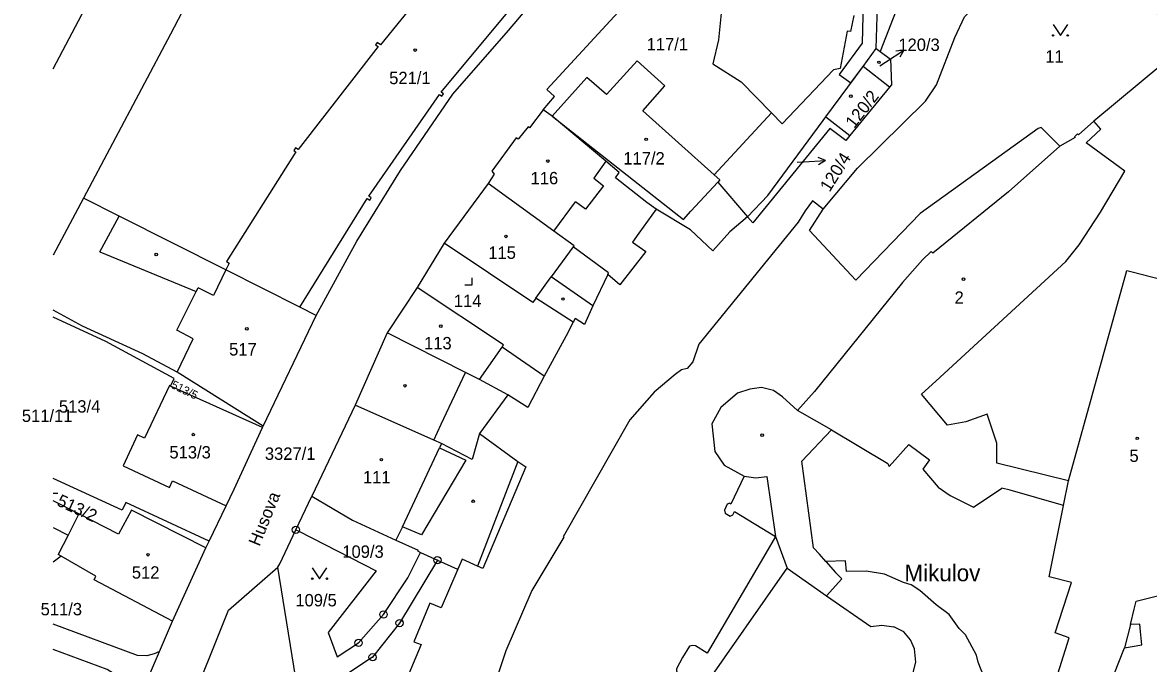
# Model space of a CAD drawing. Extents: x -600849 to -599899, y -1204328 to -1203436.
# Drawn here: x -600847.4 to -600692.7, y -1203896.5 to -1203808.4 of the extents above; entities that cross this region are included whole.
import ezdxf

# ---------------------------------------------------------------- set-up
doc = ezdxf.new("R2010")
doc.units = 0
for name, color, linetype in [('Vrstva 1', 7, 'Continuous'), ('Vrstva 13', 7, 'Continuous'), ('Vrstva 2', 7, 'Continuous'), ('Vrstva 3', 7, 'Continuous'), ('Vrstva 4', 7, 'Continuous'), ('Vrstva 5', 7, 'Continuous'), ('Vrstva 7', 7, 'Continuous'), ('Vrstva 8', 7, 'Continuous')]:
    doc.layers.add(name, color=color, linetype=linetype)

msp = doc.modelspace()

# ---------------------------------------------------------------- linework, layer by layer
at = {"layer": 'Vrstva 1'}
for p, q in [((-600727.05, -1203805.97), (-600729.55, -1203812.41)), ((-600737.03, -1203821.39), (-600731.91, -1203814.47)), ((-600728.27, -1203817.33), (-600731.91, -1203814.47)), ((-600728.27, -1203817.33), (-600733.72, -1203823.97)), ((-600774.6, -1203821.28), (-600775.84, -1203820.43)), ((-600745, -1203832.19), (-600737.4, -1203821.9)), ((-600737.4, -1203821.9), (-600737.03, -1203821.39)), ((-600737.03, -1203821.39), (-600733.72, -1203823.97)), ((-600783.42, -1203830.57), (-600789.47, -1203838.73)), ((-600839.01, -1203832.56), (-600843.16, -1203840.38)), ((-600747.78, -1203835.11), (-600745, -1203832.19)), ((-600760.31, -1203834.09), (-600762.69, -1203837.37)), ((-600807.05, -1203848.68), (-600801.44, -1203838.45)), ((-600789.47, -1203838.73), (-600793.16, -1203844.82)), ((-600771.73, -1203839.24), (-600771.6, -1203839.09)), ((-600809.28, -1203847.56), (-600819.46, -1203842.42)), ((-600793.16, -1203844.82), (-600797.28, -1203851.06)), ((-600839.14, -1203850.16), (-600843.16, -1203847.96)), ((-600814.3, -1203863.89), (-600807.05, -1203848.68)), ((-600807.05, -1203848.68), (-600809.28, -1203847.56)), ((-600830.86, -1203853.93), (-600839.14, -1203850.16)), ((-600780.72, -1203859.56), (-600784.58, -1203857.49)), ((-600814.39, -1203864.09), (-600827.03, -1203858.37)), ((-600780.72, -1203859.56), (-600784.61, -1203864.9)), ((-600738.59, -1203859.1), (-600740.89, -1203861.71)), ((-600814.39, -1203864.09), (-600814.3, -1203863.89)), ((-600784.61, -1203864.9), (-600779.31, -1203868.72)), ((-600809.81, -1203878.13), (-600807.64, -1203873.51)), ((-600821.74, -1203879.69), (-600819.41, -1203874.84)), ((-600822.18, -1203880.62), (-600821.74, -1203879.69)), ((-600826.76, -1203890.67), (-600822.18, -1203880.62)), ((-600793.09, -1203881.03), (-600792.7, -1203881.25)), ((-600792.7, -1203881.25), (-600790.38, -1203882.29)), ((-600737.9, -1203881.45), (-600738.72, -1203880.62)), ((-600734.19, -1203883.86), (-600734.3, -1203882.37)), ((-600809.25, -1203902.22), (-600812.31, -1203883.27)), ((-600826.76, -1203890.67), (-600837.53, -1203884.98)), ((-600828.56, -1203894.86), (-600826.76, -1203890.67)), ((-600831.48, -1203901.67), (-600828.56, -1203894.86))]:
    msp.add_line(p, q, dxfattribs=at)
for points in [[(-600802.64, -1203748.13), (-600803.14, -1203749.18), (-600814.03, -1203785.11), (-600827.06, -1203810.04), (-600839.01, -1203832.56)], [(-600737.38, -1203834.09), (-600732.67, -1203828.46), (-600723.35, -1203819.26), (-600721.81, -1203816.98), (-600719.31, -1203810.49), (-600717.95, -1203807.66), (-600716.14, -1203805.77), (-600712.27, -1203803.58), (-600705.39, -1203801.39), (-600697.84, -1203798.69), (-600687.98, -1203794.26), (-600682.65, -1203790.56), (-600667.7, -1203784.66)], [(-600673.9, -1203792.73), (-600675.35, -1203794.62), (-600677.86, -1203792.55), (-600681.23, -1203794.3), (-600693.25, -1203805.47), (-600687.48, -1203811.4), (-600700.22, -1203821.97)], [(-600843.16, -1203814.79), (-600834.4, -1203798.18), (-600843.16, -1203793.49)], [(-600787.03, -1203797.7), (-600798.21, -1203811.49), (-600798.63, -1203811.16), (-600798.87, -1203811.48), (-600798.52, -1203811.75), (-600809.52, -1203825.88), (-600809.86, -1203825.65), (-600810.09, -1203826.01), (-600809.82, -1203826.18), (-600819.35, -1203841.27), (-600819, -1203841.47), (-600819.46, -1203842.42)], [(-600801.44, -1203838.45), (-600795.45, -1203828.75), (-600788.25, -1203818.26), (-600780.62, -1203809.55), (-600775.47, -1203803.45), (-600771.22, -1203798.52)], [(-600775.84, -1203820.43), (-600774.28, -1203818.6), (-600775.35, -1203817.62), (-600759.61, -1203800.52), (-600755.85, -1203801.01)], [(-600755.85, -1203801.01), (-600755.86, -1203801.21), (-600756.54, -1203801.19), (-600756.54, -1203802.08), (-600754.02, -1203802.09), (-600753.97, -1203801.76), (-600750.89, -1203802.05), (-600751.77, -1203810.82), (-600752.53, -1203814.09), (-600748.64, -1203816.56), (-600744.48, -1203820.82), (-600752.36, -1203829.34)], [(-600809.28, -1203847.56), (-600800.02, -1203832.63), (-600799.67, -1203832.86), (-600799.46, -1203832.53), (-600799.81, -1203832.3), (-600790.11, -1203818.32), (-600789.79, -1203818.55), (-600789.56, -1203818.22), (-600789.87, -1203817.98), (-600778.94, -1203804.83)], [(-600731.91, -1203814.47), (-600730.1, -1203812.01), (-600729.55, -1203812.41)], [(-600729.55, -1203812.41), (-600728.12, -1203813.46), (-600728, -1203817), (-600728.27, -1203817.33)], [(-600752.36, -1203829.34), (-600762.17, -1203820.56), (-600759.15, -1203817.12), (-600762.96, -1203813.69), (-600767.14, -1203818.32), (-600769.85, -1203815.97), (-600774.6, -1203821.28)], [(-600775.84, -1203820.43), (-600777.71, -1203822.91), (-600777.92, -1203822.75), (-600779.3, -1203824.45), (-600779.56, -1203824.27), (-600782.92, -1203828.86)], [(-600765.91, -1203829.78), (-600765.41, -1203829.03), (-600767.23, -1203827.5), (-600774.6, -1203821.28)], [(-600700.22, -1203821.97), (-600702.31, -1203823.86), (-600702.44, -1203823.71), (-600702.87, -1203824.15), (-600702.76, -1203824.25), (-600704.9, -1203825.4)], [(-600701.28, -1203824.96), (-600699.26, -1203823.08), (-600700.22, -1203821.97)], [(-600733.72, -1203823.97), (-600734.29, -1203824.66), (-600736.45, -1203823.01), (-600747.06, -1203835.95), (-600747.78, -1203835.11)], [(-600704.9, -1203825.4), (-600706.94, -1203823.34), (-600707.42, -1203822.85), (-600707.87, -1203823.01), (-600724.08, -1203834.67), (-600732.9, -1203843.81), (-600739.28, -1203837), (-600737.38, -1203834.09)], [(-600704.9, -1203825.4), (-600711.93, -1203831.7), (-600722.33, -1203840.12), (-600722.54, -1203839.9), (-600723.75, -1203841.03), (-600726.51, -1203844.14), (-600738.59, -1203859.1)], [(-600699.3, -1203834.48), (-600695.97, -1203828.84), (-600701.28, -1203824.96)], [(-600782.92, -1203828.86), (-600782.59, -1203829.26), (-600783.42, -1203830.57)], [(-600760.31, -1203834.09), (-600761.62, -1203833.14), (-600765.91, -1203829.78)], [(-600752.36, -1203829.34), (-600751.58, -1203830.04), (-600751.87, -1203830.36), (-600747.78, -1203835.11)], [(-600771.6, -1203839.09), (-600774.37, -1203837.09), (-600783.42, -1203830.57)], [(-600819.46, -1203842.42), (-600834.1, -1203835.04), (-600839.01, -1203832.56)], [(-600737.38, -1203834.09), (-600738.87, -1203832.92), (-600739.85, -1203834.3), (-600740.81, -1203835.88), (-600754.48, -1203852.63), (-600755.3, -1203855.06)], [(-600747.78, -1203835.11), (-600750.21, -1203837.21), (-600752.56, -1203839.78), (-600755.62, -1203836.92), (-600760.31, -1203834.09)], [(-600723.87, -1203859.5), (-600721.91, -1203857.69), (-600704.07, -1203841.28), (-600702.22, -1203838.96), (-600699.3, -1203834.48)], [(-600762.69, -1203837.37), (-600763.6, -1203838.62), (-600761.75, -1203839.9), (-600765.31, -1203844.46), (-600766.97, -1203843.04)], [(-600771.72, -1203849.61), (-600776.85, -1203846.31), (-600777.25, -1203846.89), (-600789.47, -1203838.73)], [(-600766.97, -1203843.04), (-600766.86, -1203842.8), (-600771.73, -1203839.24)], [(-600703.69, -1203871.38), (-600695.68, -1203842.51), (-600695.14, -1203842.65), (-600690.69, -1203843.79)], [(-600766.97, -1203843.04), (-600769.03, -1203847.34), (-600770.16, -1203849.91), (-600771.46, -1203849.1), (-600771.72, -1203849.61)], [(-600775.69, -1203857.03), (-600781.5, -1203853.03), (-600781.29, -1203852.73), (-600793.16, -1203844.82)], [(-600827.03, -1203858.37), (-600826.54, -1203857.35), (-600835.91, -1203852.25), (-600843.16, -1203848.91)], [(-600771.72, -1203849.61), (-600772.69, -1203851.49), (-600775.69, -1203857.03)], [(-600797.28, -1203851.06), (-600801.66, -1203861), (-600807.64, -1203873.51)], [(-600784.58, -1203857.49), (-600786.51, -1203856.53), (-600797.28, -1203851.06)], [(-600695.18, -1203891.11), (-600694.68, -1203889.04), (-600694.39, -1203887.92), (-600690.34, -1203886.92), (-600689.28, -1203885.9), (-600688.55, -1203884.24), (-600688.96, -1203881.25), (-600688.02, -1203881.41), (-600686.37, -1203873.21), (-600684.56, -1203873.7), (-600684.15, -1203869.75), (-600685.6, -1203869.38), (-600682.53, -1203852.21)], [(-600814.3, -1203863.89), (-600826.12, -1203856.48), (-600830.86, -1203853.93)], [(-600755.3, -1203855.06), (-600756.07, -1203855.96), (-600756.84, -1203856.15), (-600757.72, -1203856.79), (-600760.58, -1203859.21), (-600763.94, -1203863)], [(-600775.69, -1203857.03), (-600777.96, -1203861.34), (-600780.72, -1203859.56)], [(-600827.03, -1203858.37), (-600827.18, -1203858.3), (-600830.62, -1203865.52), (-600831.56, -1203865.08), (-600833.54, -1203869.32), (-600827.17, -1203872.3), (-600826.75, -1203871.41), (-600819.41, -1203874.84)], [(-600745.84, -1203858.58), (-600747.47, -1203858.82), (-600749.15, -1203859.36), (-600751.46, -1203861.32), (-600752.69, -1203863.58), (-600752.27, -1203867.37), (-600750.97, -1203869.26)], [(-600740.89, -1203861.71), (-600742.96, -1203859.85), (-600744.19, -1203859), (-600745.84, -1203858.58)], [(-600714.86, -1203862.25), (-600717.79, -1203863.3), (-600720.31, -1203863.73), (-600723.87, -1203859.5)], [(-600738.72, -1203880.62), (-600740.32, -1203868.69), (-600736.22, -1203864.38), (-600740.89, -1203861.71)], [(-600703.69, -1203871.38), (-600713.55, -1203868.98), (-600713.51, -1203866.24), (-600714.86, -1203862.25)], [(-600819.41, -1203874.84), (-600818.29, -1203872.52), (-600814.39, -1203864.09)], [(-600763.94, -1203863), (-600773.1, -1203879.07), (-600772.99, -1203879.14), (-600777.42, -1203886.44), (-600780.99, -1203894.73), (-600783.52, -1203902.47), (-600784.83, -1203907.67), (-600785.24, -1203911.84), (-600785.51, -1203922.73), (-600784.83, -1203931.21)], [(-600779.31, -1203868.72), (-600778.24, -1203869.49), (-600784.16, -1203883.42), (-600784.87, -1203883.1), (-600786.99, -1203882.17), (-600787.58, -1203883.54)], [(-600750.97, -1203869.26), (-600748.24, -1203870.77), (-600750.05, -1203874.59)], [(-600821.74, -1203879.69), (-600833.16, -1203874.39), (-600833.68, -1203875.44), (-600843.16, -1203871.07)], [(-600715.32, -1203921), (-600710.97, -1203917.16), (-600710.86, -1203915.92), (-600707.36, -1203904.89), (-600708.72, -1203904.43), (-600707.81, -1203901.53), (-600706.45, -1203902), (-600703.58, -1203892.95), (-600705.52, -1203892.28), (-600703.27, -1203885.38), (-600706.32, -1203884.59), (-600704.37, -1203874.77), (-600703.69, -1203871.38)], [(-600807.64, -1203873.51), (-600802.06, -1203876.78), (-600796.07, -1203879.54)], [(-600822.18, -1203880.62), (-600832.41, -1203875.44), (-600834.19, -1203878.72), (-600839.64, -1203875.94), (-600843.16, -1203874.14)], [(-600750.05, -1203874.59), (-600750.21, -1203874.47), (-600750.59, -1203874.61), (-600750.93, -1203875.42), (-600750.87, -1203875.84)], [(-600750.87, -1203875.84), (-600750.17, -1203876.23), (-600749.78, -1203876.05), (-600749.56, -1203875.61), (-600743.94, -1203879.03), (-600745.28, -1203881.33), (-600753.32, -1203895.09), (-600754.91, -1203894.07), (-600755.28, -1203894), (-600755.73, -1203894.09), (-600756.69, -1203895.65), (-600757.54, -1203897.2), (-600757.54, -1203897.49), (-600757.43, -1203897.77), (-600755.55, -1203898.91), (-600764.93, -1203914.97)], [(-600812.31, -1203883.27), (-600812, -1203882.78), (-600809.81, -1203878.13)], [(-600809.81, -1203878.13), (-600809.42, -1203878.33), (-600798.77, -1203883.75), (-600805.4, -1203892.23), (-600804.16, -1203895.57), (-600801.2, -1203893.64), (-600797.79, -1203889.76), (-600794.42, -1203884.74), (-600792.7, -1203881.25)], [(-600796.07, -1203879.54), (-600793.03, -1203880.91), (-600793.09, -1203881.03)], [(-600734.3, -1203882.37), (-600737.01, -1203882.46), (-600737.9, -1203881.45)], [(-600837.53, -1203884.98), (-600837.28, -1203884.47), (-600842.06, -1203881.74), (-600843.16, -1203882.57)], [(-600790.38, -1203882.29), (-600795.57, -1203890.93), (-600799.28, -1203895.63), (-600809.25, -1203902.22)], [(-600790.38, -1203882.29), (-600787.62, -1203883.52), (-600787.58, -1203883.54)], [(-600824.88, -1203903.67), (-600819.09, -1203889.18), (-600812.31, -1203883.27)], [(-600787.58, -1203883.54), (-600789.86, -1203888.84), (-600791.4, -1203888.21), (-600793.62, -1203893.51), (-600792.62, -1203893.88), (-600795.05, -1203899.63), (-600790.58, -1203900.68), (-600790.6, -1203903.65), (-600793.26, -1203903.01), (-600793.31, -1203903.54), (-600790.7, -1203904.24), (-600790.71, -1203904.87), (-600793.43, -1203904.71), (-600793.41, -1203905.37), (-600790.81, -1203905.49), (-600791.3, -1203910.49), (-600798.28, -1203911.49), (-600798.81, -1203910.12), (-600799.34, -1203910.23), (-600798.91, -1203911.53), (-600803.11, -1203912.34)], [(-600721.63, -1203913.91), (-600720.73, -1203913.53), (-600719.73, -1203912.59), (-600719.28, -1203911.86), (-600718.71, -1203911.03), (-600717.34, -1203907.4), (-600716.32, -1203905.14), (-600715.97, -1203902.37), (-600715.44, -1203900.22), (-600715.17, -1203898.49), (-600715.7, -1203897.34), (-600716.11, -1203896.32), (-600716.32, -1203895.35), (-600717.85, -1203892.57), (-600718.69, -1203891.67), (-600720.06, -1203889.76), (-600721.86, -1203888.42), (-600724.12, -1203886.44), (-600725.3, -1203885.67), (-600726.35, -1203885.35), (-600728.96, -1203884.22), (-600731.48, -1203883.79), (-600734.19, -1203883.86)], [(-600828.56, -1203894.86), (-600829.27, -1203895.16), (-600830.27, -1203895.42), (-600831.58, -1203895.4), (-600843.16, -1203891.09)], [(-600702.77, -1203919.65), (-600695.52, -1203898.79), (-600697.44, -1203898.03), (-600695.99, -1203894.35), (-600693.6, -1203893.94), (-600693.78, -1203892.09)], [(-600693.78, -1203892.09), (-600693.88, -1203891.09), (-600695.18, -1203891.11)], [(-600831.48, -1203901.67), (-600832.07, -1203900.59), (-600833.17, -1203899.21), (-600834.22, -1203898.26), (-600835.73, -1203897.33), (-600843.16, -1203894.56)]]:
    msp.add_lwpolyline(points, dxfattribs=at)
at = {"layer": 'Vrstva 13'}
msp.add_lwpolyline([(-600729.88, -1203804.64), (-600731.83, -1203803.72), (-600732.02, -1203811.26), (-600735.19, -1203815.56), (-600733.58, -1203816.72), (-600731.91, -1203814.47), (-600730.1, -1203812.01)], close=True, dxfattribs=at)
at = {"layer": 'Vrstva 3'}
for p, q in [((-600785.6, -1203844.49), (-600785.6, -1203843.49)), ((-600786.6, -1203844.49), (-600785.6, -1203844.49)), ((-600843.16, -1203873.08), (-600842.5, -1203873.08))]:
    msp.add_line(p, q, dxfattribs=at)
for points in [[(-600705.8, -1203808.71), (-600704.8, -1203810.21), (-600703.8, -1203808.71)], [(-600807.56, -1203883.34), (-600806.56, -1203884.84), (-600805.56, -1203883.34)]]:
    msp.add_lwpolyline(points, dxfattribs=at)
for centre in [(-600705.8, -1203810.21), (-600703.8, -1203810.21), (-600807.56, -1203884.84), (-600805.56, -1203884.84)]:
    msp.add_circle(centre, 0.1, dxfattribs=at)
at = {"layer": 'Vrstva 4'}
for p, q in [((-600733.18, -1203807.46), (-600733.61, -1203809.69)), ((-600734.08, -1203809.6), (-600735.07, -1203814.73)), ((-600733.61, -1203809.69), (-600734.08, -1203809.6)), ((-600735.96, -1203814.95), (-600743.03, -1203822.35)), ((-600735.07, -1203814.73), (-600735.96, -1203814.95)), ((-600743.03, -1203822.35), (-600744.48, -1203820.82)), ((-600774.6, -1203821.28), (-600756.59, -1203835.51)), ((-600767.23, -1203827.5), (-600768.87, -1203829.81)), ((-600768.87, -1203829.81), (-600767.57, -1203830.87)), ((-600751.87, -1203830.36), (-600755.55, -1203834.37)), ((-600767.57, -1203830.87), (-600770.05, -1203834.07)), ((-600774.37, -1203837.09), (-600771.39, -1203833.08)), ((-600770.05, -1203834.07), (-600771.39, -1203833.08)), ((-600836.77, -1203839.93), (-600834.1, -1203835.04)), ((-600756.59, -1203835.51), (-600755.55, -1203834.37)), ((-600771.73, -1203839.24), (-600774.77, -1203843.37)), ((-600836.77, -1203839.93), (-600823.5, -1203845.39)), ((-600819.46, -1203842.42), (-600821.12, -1203845.93)), ((-600776.85, -1203846.31), (-600774.77, -1203843.37)), ((-600769.03, -1203847.34), (-600774.77, -1203843.37)), ((-600826.19, -1203850.68), (-600823.5, -1203845.39)), ((-600823.5, -1203845.39), (-600823.24, -1203844.88)), ((-600821.12, -1203845.93), (-600823.24, -1203844.88)), ((-600823.93, -1203851.87), (-600826.19, -1203850.68)), ((-600826.12, -1203856.48), (-600823.93, -1203851.87)), ((-600784.58, -1203857.49), (-600781.5, -1203853.03)), ((-600789.86, -1203863.61), (-600786.51, -1203856.53)), ((-600790.89, -1203865.79), (-600801.66, -1203861)), ((-600790.89, -1203865.79), (-600789.86, -1203863.61)), ((-600736.22, -1203864.38), (-600728.5, -1203869)), ((-600789.8, -1203866.27), (-600790.89, -1203865.79)), ((-600784.61, -1203864.9), (-600785.6, -1203868.47)), ((-600795.16, -1203877.71), (-600790.07, -1203866.84)), ((-600789.8, -1203866.27), (-600790.07, -1203866.84)), ((-600790.07, -1203866.84), (-600786.46, -1203868.56)), ((-600785.6, -1203868.47), (-600789.8, -1203866.27)), ((-600728.3, -1203869.41), (-600725.63, -1203866.42)), ((-600725.63, -1203866.42), (-600722.78, -1203868.53)), ((-600786.46, -1203868.56), (-600792.58, -1203878.8)), ((-600779.31, -1203868.72), (-600784.87, -1203883.1)), ((-600728.5, -1203869), (-600728.3, -1203869.41)), ((-600722.78, -1203868.53), (-600723.71, -1203869.79)), ((-600723.71, -1203869.79), (-600721.59, -1203872.26)), ((-600748.24, -1203870.77), (-600746.62, -1203870.99)), ((-600746.62, -1203870.99), (-600745.12, -1203870.8)), ((-600745.12, -1203870.8), (-600743.94, -1203879.03)), ((-600721.59, -1203872.26), (-600719.96, -1203873.41)), ((-600719.96, -1203873.41), (-600716.74, -1203875.01)), ((-600716.74, -1203875.01), (-600712.83, -1203872.41)), ((-600711.69, -1203872.67), (-600712.83, -1203872.41)), ((-600704.37, -1203874.77), (-600711.69, -1203872.67)), ((-600839.64, -1203875.94), (-600841.11, -1203878.86)), ((-600843.16, -1203877.79), (-600841.11, -1203878.86)), ((-600795.16, -1203877.71), (-600796.07, -1203879.54)), ((-600792.58, -1203878.8), (-600795.16, -1203877.71)), ((-600841.11, -1203878.86), (-600842.45, -1203881.52)), ((-600743.94, -1203879.03), (-600742.35, -1203883.41)), ((-600842.06, -1203881.74), (-600842.45, -1203881.52)), ((-600737.01, -1203882.46), (-600735.68, -1203883.97)), ((-600764.48, -1203915.04), (-600742.35, -1203883.41)), ((-600742.35, -1203883.41), (-600736.91, -1203887.2)), ((-600735.68, -1203883.97), (-600734.82, -1203884.86)), ((-600734.82, -1203884.86), (-600736.91, -1203887.2)), ((-600736.91, -1203887.2), (-600730.85, -1203891.41)), ((-600730.85, -1203891.41), (-600729.33, -1203891.2)), ((-600729.33, -1203891.2), (-600727.66, -1203891.47)), ((-600726.29, -1203892.16), (-600727.66, -1203891.47)), ((-600725.41, -1203893.22), (-600726.29, -1203892.16)), ((-600695.18, -1203891.11), (-600695.99, -1203894.35)), ((-600724.82, -1203894.49), (-600725.41, -1203893.22)), ((-600724.67, -1203896.29), (-600724.82, -1203894.49)), ((-600725.08, -1203897.91), (-600724.67, -1203896.29))]:
    msp.add_line(p, q, dxfattribs=at)
at = {"layer": 'Vrstva 5'}
for centre in [(-600793.43, -1203812.22), (-600729.73, -1203813.91), (-600733.59, -1203818.56), (-600761.7, -1203824.48), (-600775.21, -1203827.47), (-600780.96, -1203837.82), (-600829, -1203840.31), (-600718.11, -1203843.69), (-600773.13, -1203846.42), (-600816.56, -1203850.52), (-600789.92, -1203850.14), (-600794.83, -1203858.33), (-600823.91, -1203865.04), (-600745.77, -1203865.12), (-600694.24, -1203865.55), (-600798.08, -1203868.49), (-600785.46, -1203874.2), (-600830.13, -1203881.55)]:
    msp.add_circle(centre, 0.175, dxfattribs=at)
at = {"layer": 'Vrstva 7'}
for p, q in [((-600728.81, -1203813.87), (-600726.29, -1203812.24)), ((-600726.29, -1203812.24), (-600727.41, -1203812.36)), ((-600726.29, -1203812.24), (-600726.86, -1203813.2)), ((-600729.6, -1203814.38), (-600728.81, -1203813.87)), ((-600737.06, -1203827.41), (-600738.09, -1203826.97)), ((-600740.98, -1203827.62), (-600740.06, -1203827.57)), ((-600740.06, -1203827.57), (-600737.06, -1203827.41)), ((-600737.06, -1203827.41), (-600738.04, -1203827.97))]:
    msp.add_line(p, q, dxfattribs=at)
at = {"layer": 'Vrstva 8'}
for centre, radius in [((-600809.81, -1203878.13), 0.5), ((-600809.81, -1203878.13), 0.0303), ((-600790.38, -1203882.29), 0.5), ((-600790.38, -1203882.29), 0.0303), ((-600797.79, -1203889.76), 0.5), ((-600797.79, -1203889.76), 0.0303), ((-600795.57, -1203890.93), 0.5), ((-600795.57, -1203890.93), 0.0303), ((-600801.2, -1203893.64), 0.5), ((-600801.2, -1203893.64), 0.0303), ((-600799.28, -1203895.63), 0.5), ((-600799.28, -1203895.63), 0.0303)]:
    msp.add_circle(centre, radius, dxfattribs=at)

# ---------------------------------------------------------------- texts
at = {"layer": 'Vrstva 2'}
for s, p in [('117/1', (-600761.64, -1203812.27)), ('120/3', (-600727.06, -1203812.34)), ('11', (-600706.87, -1203813.94)), ('521/1', (-600797, -1203816.9)), ('117/2', (-600764.84, -1203827.94)), ('116', (-600777.58, -1203830.66)), ('115', (-600783.39, -1203840.9)), ('114', (-600788.12, -1203847.52)), ('2', (-600719.34, -1203847.07)), ('113', (-600792.21, -1203853.33)), ('517', (-600818.99, -1203854.18)), ('513/4', (-600842.37, -1203862.02)), ('511/11', (-600847.46, -1203863.3)), ('513/3', (-600827.19, -1203868.32)), ('3327/1', (-600814.08, -1203868.51)), ('5', (-600695.31, -1203868.8)), ('111', (-600800.61, -1203871.74)), ('109/3', (-600803.44, -1203881.97)), ('512', (-600832.35, -1203884.83)), ('109/5', (-600809.89, -1203888.64)), ('511/3', (-600844.88, -1203889.87))]:
    msp.add_text(s, height=1.7, dxfattribs=at).set_placement(p)
for s, height, rotation, p in [('120/2', 1.7, 52, (-600733.13, -1203823.08)), ('120/4', 1.7, 58, (-600736.5, -1203831.82)), ('513/5', 1.14, 334, (-600827.06, -1203858.58)), ('513/2', 1.7, 335, (-600842.79, -1203874.71))]:
    msp.add_text(s, height=height, rotation=rotation, dxfattribs=at).set_placement(p)
at = {"layer": 'Vrstva 7'}
msp.add_text('Husova', height=1.7, rotation=68, dxfattribs=at).set_placement((-600814.82, -1203880.48))
msp.add_text('Mikulov', height=2.3, dxfattribs=at).set_placement((-600726.22, -1203885.19))

doc.saveas('drawing.dxf')
